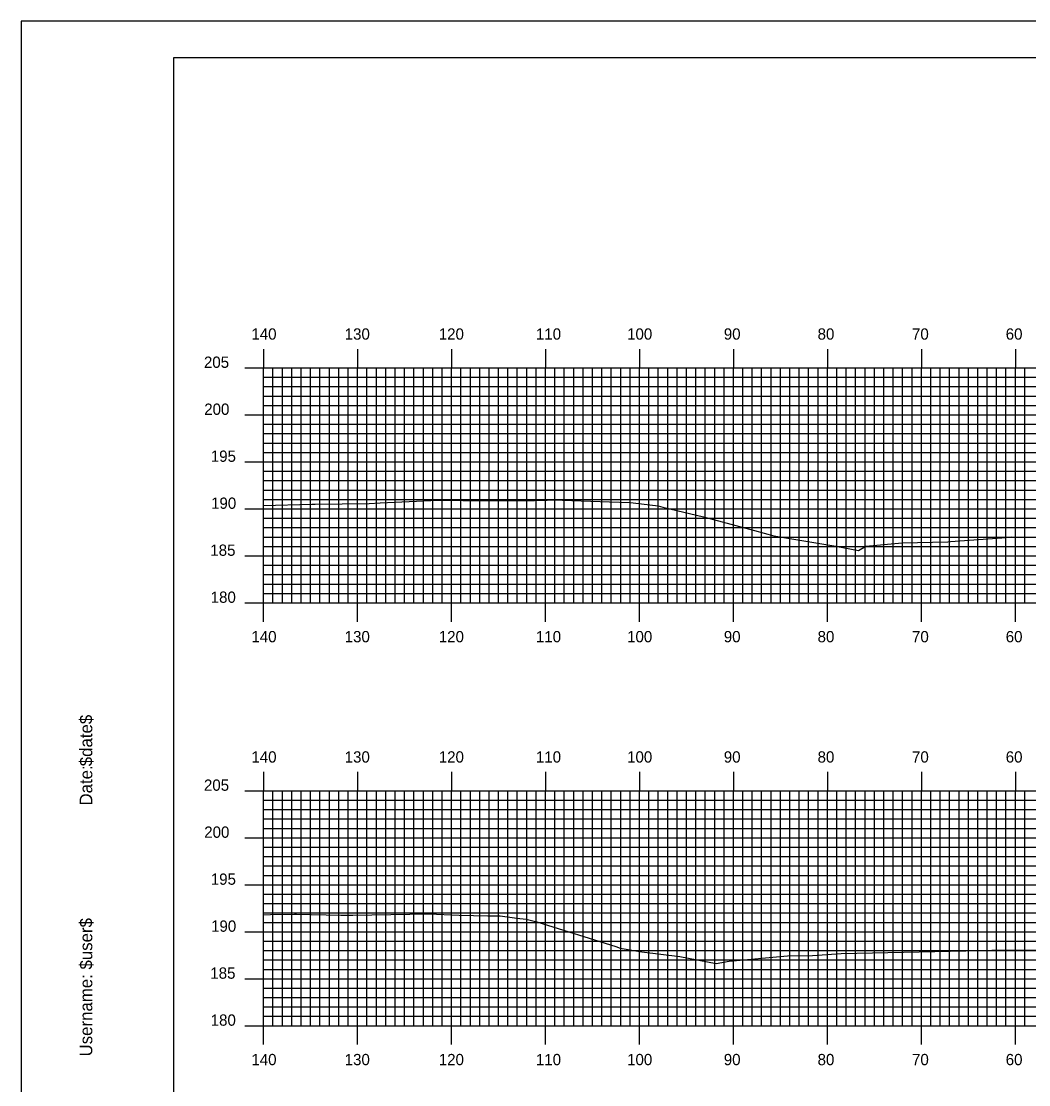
# Model space of a CAD drawing. Extents: x 1822392 to 1822735, y 442591 to 442811.
# Drawn here: x 1822392 to 1822499.2, y 442697.4 to 442810.5 of the extents above; entities that cross this region are included whole.
import ezdxf

# ---------------------------------------------------------------- set-up
doc = ezdxf.new("R2010")
doc.units = 0
for name, color, linetype in [('BORDER', 7, 'Continuous'), ('H_V ANNOTATION', 7, 'Continuous'), ('MAJOR', 7, 'Continuous'), ('MINOR', 7, 'Continuous'), ('PLOT BOUNDARY', 7, 'Continuous'), ('S_Roadway_Centerline', 7, 'Continuous')]:
    doc.layers.add(name, color=color, linetype=linetype)

msp = doc.modelspace()

# ---------------------------------------------------------------- linework, layer by layer
at = {"layer": 'BORDER'}
msp.add_lwpolyline([(1822408.17, 442596.67), (1822728.17, 442596.67), (1822728.17, 442806.67), (1822408.17, 442806.67)], close=True, dxfattribs=at)
at = {"layer": 'MAJOR'}
for p, q in [((1822417.77, 442775.67), (1822417.77, 442773.67)), ((1822427.77, 442775.67), (1822427.77, 442773.67)), ((1822437.77, 442775.67), (1822437.77, 442773.67)), ((1822447.77, 442775.67), (1822447.77, 442773.67)), ((1822457.77, 442775.67), (1822457.77, 442773.67)), ((1822467.77, 442775.67), (1822467.77, 442773.67)), ((1822477.77, 442775.67), (1822477.77, 442773.67)), ((1822487.77, 442775.67), (1822487.77, 442773.67)), ((1822497.77, 442775.67), (1822497.77, 442773.67)), ((1822415.77, 442773.67), (1822417.77, 442773.67)), ((1822417.77, 442773.67), (1822697.77, 442773.67)), ((1822417.77, 442748.67), (1822417.77, 442773.67)), ((1822417.77, 442748.67), (1822417.77, 442773.67)), ((1822417.77, 442773.67), (1822697.77, 442773.67)), ((1822427.77, 442748.67), (1822427.77, 442773.67)), ((1822437.77, 442748.67), (1822437.77, 442773.67)), ((1822447.77, 442748.67), (1822447.77, 442773.67)), ((1822457.77, 442748.67), (1822457.77, 442773.67)), ((1822467.77, 442748.67), (1822467.77, 442773.67)), ((1822477.77, 442748.67), (1822477.77, 442773.67)), ((1822487.77, 442748.67), (1822487.77, 442773.67)), ((1822497.77, 442748.67), (1822497.77, 442773.67)), ((1822415.77, 442768.67), (1822417.77, 442768.67)), ((1822417.77, 442768.67), (1822697.77, 442768.67)), ((1822415.77, 442763.67), (1822417.77, 442763.67)), ((1822417.77, 442763.67), (1822697.77, 442763.67)), ((1822415.77, 442758.67), (1822417.77, 442758.67)), ((1822417.77, 442758.67), (1822697.77, 442758.67)), ((1822415.77, 442753.67), (1822417.77, 442753.67)), ((1822417.77, 442753.67), (1822697.77, 442753.67)), ((1822415.77, 442748.67), (1822417.77, 442748.67)), ((1822417.77, 442748.67), (1822697.77, 442748.67)), ((1822417.77, 442748.67), (1822697.77, 442748.67)), ((1822417.77, 442746.66), (1822417.77, 442748.67)), ((1822427.77, 442746.66), (1822427.77, 442748.67)), ((1822437.77, 442746.66), (1822437.77, 442748.67)), ((1822447.77, 442746.66), (1822447.77, 442748.67)), ((1822457.77, 442746.66), (1822457.77, 442748.67)), ((1822467.77, 442746.66), (1822467.77, 442748.67)), ((1822477.77, 442746.66), (1822477.77, 442748.67)), ((1822487.77, 442746.66), (1822487.77, 442748.67)), ((1822497.77, 442746.66), (1822497.77, 442748.67)), ((1822417.77, 442730.67), (1822417.77, 442728.67)), ((1822427.77, 442730.67), (1822427.77, 442728.67)), ((1822437.77, 442730.67), (1822437.77, 442728.67)), ((1822447.77, 442730.67), (1822447.77, 442728.67)), ((1822457.77, 442730.67), (1822457.77, 442728.67)), ((1822467.77, 442730.67), (1822467.77, 442728.67)), ((1822477.77, 442730.67), (1822477.77, 442728.67)), ((1822487.77, 442730.67), (1822487.77, 442728.67)), ((1822497.77, 442730.67), (1822497.77, 442728.67)), ((1822415.77, 442728.67), (1822417.77, 442728.67)), ((1822417.77, 442728.67), (1822697.77, 442728.67)), ((1822417.77, 442703.67), (1822417.77, 442728.67)), ((1822417.77, 442703.67), (1822417.77, 442728.67)), ((1822417.77, 442728.67), (1822697.77, 442728.67)), ((1822427.77, 442703.67), (1822427.77, 442728.67)), ((1822437.77, 442703.67), (1822437.77, 442728.67)), ((1822447.77, 442703.67), (1822447.77, 442728.67)), ((1822457.77, 442703.67), (1822457.77, 442728.67)), ((1822467.77, 442703.67), (1822467.77, 442728.67)), ((1822477.77, 442703.67), (1822477.77, 442728.67)), ((1822487.77, 442703.67), (1822487.77, 442728.67)), ((1822497.77, 442703.67), (1822497.77, 442728.67)), ((1822415.77, 442723.67), (1822417.77, 442723.67)), ((1822417.77, 442723.67), (1822697.77, 442723.67)), ((1822415.77, 442718.67), (1822417.77, 442718.67)), ((1822417.77, 442718.67), (1822697.77, 442718.67)), ((1822415.77, 442713.67), (1822417.77, 442713.67)), ((1822417.77, 442713.67), (1822697.77, 442713.67)), ((1822415.77, 442708.67), (1822417.77, 442708.67)), ((1822417.77, 442708.67), (1822697.77, 442708.67)), ((1822415.77, 442703.67), (1822417.77, 442703.67)), ((1822417.77, 442703.67), (1822697.77, 442703.67)), ((1822417.77, 442703.67), (1822697.77, 442703.67)), ((1822417.77, 442701.66), (1822417.77, 442703.67)), ((1822427.77, 442701.66), (1822427.77, 442703.67)), ((1822437.77, 442701.66), (1822437.77, 442703.67)), ((1822447.77, 442701.66), (1822447.77, 442703.67)), ((1822457.77, 442701.66), (1822457.77, 442703.67)), ((1822467.77, 442701.66), (1822467.77, 442703.67)), ((1822477.77, 442701.66), (1822477.77, 442703.67)), ((1822487.77, 442701.66), (1822487.77, 442703.67)), ((1822497.77, 442701.66), (1822497.77, 442703.67))]:
    msp.add_line(p, q, dxfattribs=at)
at = {"layer": 'MINOR'}
for p, q in [((1822417.77, 442772.67), (1822697.77, 442772.67)), ((1822417.77, 442772.67), (1822419.77, 442772.67)), ((1822418.77, 442748.67), (1822418.77, 442773.67)), ((1822419.77, 442748.67), (1822419.77, 442773.67)), ((1822420.77, 442748.67), (1822420.77, 442773.67)), ((1822421.77, 442748.67), (1822421.77, 442773.67)), ((1822422.77, 442748.67), (1822422.77, 442773.67)), ((1822423.77, 442748.67), (1822423.77, 442773.67)), ((1822424.77, 442748.67), (1822424.77, 442773.67)), ((1822425.77, 442748.67), (1822425.77, 442773.67)), ((1822426.77, 442748.67), (1822426.77, 442773.67)), ((1822428.77, 442748.67), (1822428.77, 442773.67)), ((1822429.77, 442748.67), (1822429.77, 442773.67)), ((1822430.77, 442748.67), (1822430.77, 442773.67)), ((1822431.77, 442748.67), (1822431.77, 442773.67)), ((1822432.77, 442748.67), (1822432.77, 442773.67)), ((1822433.77, 442748.67), (1822433.77, 442773.67)), ((1822434.77, 442748.67), (1822434.77, 442773.67)), ((1822435.77, 442748.67), (1822435.77, 442773.67)), ((1822436.77, 442748.67), (1822436.77, 442773.67)), ((1822438.77, 442748.67), (1822438.77, 442773.67)), ((1822439.77, 442748.67), (1822439.77, 442773.67)), ((1822440.77, 442748.67), (1822440.77, 442773.67)), ((1822441.77, 442748.67), (1822441.77, 442773.67)), ((1822442.77, 442748.67), (1822442.77, 442773.67)), ((1822443.77, 442748.67), (1822443.77, 442773.67)), ((1822444.77, 442748.67), (1822444.77, 442773.67)), ((1822445.77, 442748.67), (1822445.77, 442773.67)), ((1822446.77, 442748.67), (1822446.77, 442773.67)), ((1822448.77, 442748.67), (1822448.77, 442773.67)), ((1822449.77, 442748.67), (1822449.77, 442773.67)), ((1822450.77, 442748.67), (1822450.77, 442773.67)), ((1822451.77, 442748.67), (1822451.77, 442773.67)), ((1822452.77, 442748.67), (1822452.77, 442773.67)), ((1822453.77, 442748.67), (1822453.77, 442773.67)), ((1822454.77, 442748.67), (1822454.77, 442773.67)), ((1822455.77, 442748.67), (1822455.77, 442773.67)), ((1822456.77, 442748.67), (1822456.77, 442773.67)), ((1822458.77, 442748.67), (1822458.77, 442773.67)), ((1822459.77, 442748.67), (1822459.77, 442773.67)), ((1822460.77, 442748.67), (1822460.77, 442773.67)), ((1822461.77, 442748.67), (1822461.77, 442773.67)), ((1822462.77, 442748.67), (1822462.77, 442773.67)), ((1822463.77, 442748.67), (1822463.77, 442773.67)), ((1822464.77, 442748.67), (1822464.77, 442773.67)), ((1822465.77, 442748.67), (1822465.77, 442773.67)), ((1822466.77, 442748.67), (1822466.77, 442773.67)), ((1822468.77, 442748.67), (1822468.77, 442773.67)), ((1822469.77, 442748.67), (1822469.77, 442773.67)), ((1822470.77, 442748.67), (1822470.77, 442773.67)), ((1822471.77, 442748.67), (1822471.77, 442773.67)), ((1822472.77, 442748.67), (1822472.77, 442773.67)), ((1822473.77, 442748.67), (1822473.77, 442773.67)), ((1822474.77, 442748.67), (1822474.77, 442773.67)), ((1822475.77, 442748.67), (1822475.77, 442773.67)), ((1822476.77, 442748.67), (1822476.77, 442773.67)), ((1822478.77, 442748.67), (1822478.77, 442773.67)), ((1822479.77, 442748.67), (1822479.77, 442773.67)), ((1822480.77, 442748.67), (1822480.77, 442773.67)), ((1822481.77, 442748.67), (1822481.77, 442773.67)), ((1822482.77, 442748.67), (1822482.77, 442773.67)), ((1822483.77, 442748.67), (1822483.77, 442773.67)), ((1822484.77, 442748.67), (1822484.77, 442773.67)), ((1822485.77, 442748.67), (1822485.77, 442773.67)), ((1822486.77, 442748.67), (1822486.77, 442773.67)), ((1822488.77, 442748.67), (1822488.77, 442773.67)), ((1822489.77, 442748.67), (1822489.77, 442773.67)), ((1822490.77, 442748.67), (1822490.77, 442773.67)), ((1822491.77, 442748.67), (1822491.77, 442773.67)), ((1822492.77, 442748.67), (1822492.77, 442773.67)), ((1822493.77, 442748.67), (1822493.77, 442773.67)), ((1822494.77, 442748.67), (1822494.77, 442773.67)), ((1822495.77, 442748.67), (1822495.77, 442773.67)), ((1822496.77, 442748.67), (1822496.77, 442773.67)), ((1822498.77, 442748.67), (1822498.77, 442773.67)), ((1822417.77, 442771.67), (1822697.77, 442771.67)), ((1822417.77, 442771.67), (1822419.77, 442771.67)), ((1822417.77, 442770.67), (1822697.77, 442770.67)), ((1822417.77, 442770.67), (1822419.77, 442770.67)), ((1822417.77, 442769.67), (1822697.77, 442769.67)), ((1822417.77, 442769.67), (1822419.77, 442769.67)), ((1822417.77, 442767.67), (1822697.77, 442767.67)), ((1822417.77, 442767.67), (1822419.77, 442767.67)), ((1822417.77, 442766.67), (1822697.77, 442766.67)), ((1822417.77, 442766.67), (1822419.77, 442766.67)), ((1822417.77, 442765.67), (1822697.77, 442765.67)), ((1822417.77, 442765.67), (1822419.77, 442765.67)), ((1822417.77, 442764.67), (1822697.77, 442764.67)), ((1822417.77, 442764.67), (1822419.77, 442764.67)), ((1822417.77, 442762.67), (1822697.77, 442762.67)), ((1822417.77, 442762.67), (1822419.77, 442762.67)), ((1822417.77, 442761.67), (1822697.77, 442761.67)), ((1822417.77, 442761.67), (1822419.77, 442761.67)), ((1822417.77, 442760.67), (1822697.77, 442760.67)), ((1822417.77, 442760.67), (1822419.77, 442760.67)), ((1822417.77, 442759.67), (1822697.77, 442759.67)), ((1822417.77, 442759.67), (1822419.77, 442759.67)), ((1822417.77, 442757.67), (1822697.77, 442757.67)), ((1822417.77, 442757.67), (1822419.77, 442757.67)), ((1822417.77, 442756.67), (1822697.77, 442756.67)), ((1822417.77, 442756.67), (1822419.77, 442756.67)), ((1822417.77, 442755.67), (1822697.77, 442755.67)), ((1822417.77, 442755.67), (1822419.77, 442755.67)), ((1822417.77, 442754.67), (1822697.77, 442754.67)), ((1822417.77, 442754.67), (1822419.77, 442754.67)), ((1822417.77, 442752.67), (1822697.77, 442752.67)), ((1822417.77, 442752.67), (1822419.77, 442752.67)), ((1822417.77, 442751.67), (1822697.77, 442751.67)), ((1822417.77, 442751.67), (1822419.77, 442751.67)), ((1822417.77, 442750.67), (1822697.77, 442750.67)), ((1822417.77, 442750.67), (1822419.77, 442750.67)), ((1822417.77, 442749.67), (1822697.77, 442749.67)), ((1822417.77, 442749.67), (1822419.77, 442749.67)), ((1822418.77, 442703.67), (1822418.77, 442728.67)), ((1822419.77, 442703.67), (1822419.77, 442728.67)), ((1822420.77, 442703.67), (1822420.77, 442728.67)), ((1822421.77, 442703.67), (1822421.77, 442728.67)), ((1822422.77, 442703.67), (1822422.77, 442728.67)), ((1822423.77, 442703.67), (1822423.77, 442728.67)), ((1822424.77, 442703.67), (1822424.77, 442728.67)), ((1822425.77, 442703.67), (1822425.77, 442728.67)), ((1822426.77, 442703.67), (1822426.77, 442728.67)), ((1822428.77, 442703.67), (1822428.77, 442728.67)), ((1822429.77, 442703.67), (1822429.77, 442728.67)), ((1822430.77, 442703.67), (1822430.77, 442728.67)), ((1822431.77, 442703.67), (1822431.77, 442728.67)), ((1822432.77, 442703.67), (1822432.77, 442728.67)), ((1822433.77, 442703.67), (1822433.77, 442728.67)), ((1822434.77, 442703.67), (1822434.77, 442728.67)), ((1822435.77, 442703.67), (1822435.77, 442728.67)), ((1822436.77, 442703.67), (1822436.77, 442728.67)), ((1822438.77, 442703.67), (1822438.77, 442728.67)), ((1822439.77, 442703.67), (1822439.77, 442728.67)), ((1822440.77, 442703.67), (1822440.77, 442728.67)), ((1822441.77, 442703.67), (1822441.77, 442728.67)), ((1822442.77, 442703.67), (1822442.77, 442728.67)), ((1822443.77, 442703.67), (1822443.77, 442728.67)), ((1822444.77, 442703.67), (1822444.77, 442728.67)), ((1822445.77, 442703.67), (1822445.77, 442728.67)), ((1822446.77, 442703.67), (1822446.77, 442728.67)), ((1822448.77, 442703.67), (1822448.77, 442728.67)), ((1822449.77, 442703.67), (1822449.77, 442728.67)), ((1822450.77, 442703.67), (1822450.77, 442728.67)), ((1822451.77, 442703.67), (1822451.77, 442728.67)), ((1822452.77, 442703.67), (1822452.77, 442728.67)), ((1822453.77, 442703.67), (1822453.77, 442728.67)), ((1822454.77, 442703.67), (1822454.77, 442728.67)), ((1822455.77, 442703.67), (1822455.77, 442728.67)), ((1822456.77, 442703.67), (1822456.77, 442728.67)), ((1822458.77, 442703.67), (1822458.77, 442728.67)), ((1822459.77, 442703.67), (1822459.77, 442728.67)), ((1822460.77, 442703.67), (1822460.77, 442728.67)), ((1822461.77, 442703.67), (1822461.77, 442728.67)), ((1822462.77, 442703.67), (1822462.77, 442728.67)), ((1822463.77, 442703.67), (1822463.77, 442728.67)), ((1822464.77, 442703.67), (1822464.77, 442728.67)), ((1822465.77, 442703.67), (1822465.77, 442728.67)), ((1822466.77, 442703.67), (1822466.77, 442728.67)), ((1822468.77, 442703.67), (1822468.77, 442728.67)), ((1822469.77, 442703.67), (1822469.77, 442728.67)), ((1822470.77, 442703.67), (1822470.77, 442728.67)), ((1822471.77, 442703.67), (1822471.77, 442728.67)), ((1822472.77, 442703.67), (1822472.77, 442728.67)), ((1822473.77, 442703.67), (1822473.77, 442728.67)), ((1822474.77, 442703.67), (1822474.77, 442728.67)), ((1822475.77, 442703.67), (1822475.77, 442728.67)), ((1822476.77, 442703.67), (1822476.77, 442728.67)), ((1822478.77, 442703.67), (1822478.77, 442728.67)), ((1822479.77, 442703.67), (1822479.77, 442728.67)), ((1822480.77, 442703.67), (1822480.77, 442728.67)), ((1822481.77, 442703.67), (1822481.77, 442728.67)), ((1822482.77, 442703.67), (1822482.77, 442728.67)), ((1822483.77, 442703.67), (1822483.77, 442728.67)), ((1822484.77, 442703.67), (1822484.77, 442728.67)), ((1822485.77, 442703.67), (1822485.77, 442728.67)), ((1822486.77, 442703.67), (1822486.77, 442728.67)), ((1822488.77, 442703.67), (1822488.77, 442728.67)), ((1822489.77, 442703.67), (1822489.77, 442728.67)), ((1822490.77, 442703.67), (1822490.77, 442728.67)), ((1822491.77, 442703.67), (1822491.77, 442728.67)), ((1822492.77, 442703.67), (1822492.77, 442728.67)), ((1822493.77, 442703.67), (1822493.77, 442728.67)), ((1822494.77, 442703.67), (1822494.77, 442728.67)), ((1822495.77, 442703.67), (1822495.77, 442728.67)), ((1822496.77, 442703.67), (1822496.77, 442728.67)), ((1822498.77, 442703.67), (1822498.77, 442728.67)), ((1822417.77, 442727.67), (1822697.77, 442727.67)), ((1822417.77, 442727.67), (1822419.77, 442727.67)), ((1822417.77, 442726.67), (1822697.77, 442726.67)), ((1822417.77, 442726.67), (1822419.77, 442726.67)), ((1822417.77, 442725.67), (1822697.77, 442725.67)), ((1822417.77, 442725.67), (1822419.77, 442725.67)), ((1822417.77, 442724.67), (1822697.77, 442724.67)), ((1822417.77, 442724.67), (1822419.77, 442724.67)), ((1822417.77, 442722.67), (1822697.77, 442722.67)), ((1822417.77, 442722.67), (1822419.77, 442722.67)), ((1822417.77, 442721.67), (1822697.77, 442721.67)), ((1822417.77, 442721.67), (1822419.77, 442721.67)), ((1822417.77, 442720.67), (1822697.77, 442720.67)), ((1822417.77, 442720.67), (1822419.77, 442720.67)), ((1822417.77, 442719.67), (1822697.77, 442719.67)), ((1822417.77, 442719.67), (1822419.77, 442719.67)), ((1822417.77, 442717.67), (1822697.77, 442717.67)), ((1822417.77, 442717.67), (1822419.77, 442717.67)), ((1822417.77, 442716.67), (1822697.77, 442716.67)), ((1822417.77, 442716.67), (1822419.77, 442716.67)), ((1822417.77, 442715.67), (1822697.77, 442715.67)), ((1822417.77, 442715.67), (1822419.77, 442715.67)), ((1822417.77, 442714.67), (1822697.77, 442714.67)), ((1822417.77, 442714.67), (1822419.77, 442714.67)), ((1822417.77, 442712.67), (1822697.77, 442712.67)), ((1822417.77, 442712.67), (1822419.77, 442712.67)), ((1822417.77, 442711.67), (1822697.77, 442711.67)), ((1822417.77, 442711.67), (1822419.77, 442711.67)), ((1822417.77, 442710.67), (1822697.77, 442710.67)), ((1822417.77, 442710.67), (1822419.77, 442710.67)), ((1822417.77, 442709.67), (1822697.77, 442709.67)), ((1822417.77, 442709.67), (1822419.77, 442709.67)), ((1822417.77, 442707.67), (1822697.77, 442707.67)), ((1822417.77, 442707.67), (1822419.77, 442707.67)), ((1822417.77, 442706.67), (1822697.77, 442706.67)), ((1822417.77, 442706.67), (1822419.77, 442706.67)), ((1822417.77, 442705.67), (1822697.77, 442705.67)), ((1822417.77, 442705.67), (1822419.77, 442705.67)), ((1822417.77, 442704.67), (1822697.77, 442704.67)), ((1822417.77, 442704.67), (1822419.77, 442704.67))]:
    msp.add_line(p, q, dxfattribs=at)
at = {"layer": 'PLOT BOUNDARY'}
msp.add_lwpolyline([(1822391.98, 442590.55), (1822731.98, 442590.55), (1822731.98, 442810.55), (1822391.98, 442810.55)], close=True, dxfattribs=at)
at = {"layer": 'S_Roadway_Centerline'}
for points in [[(1822417.77, 442759.04), (1822422.9, 442759.17), (1822423.24, 442759.18), (1822429, 442759.24), (1822430.19, 442759.29), (1822435.58, 442759.57), (1822435.69, 442759.6), (1822438.96, 442759.56), (1822446.59, 442759.55), (1822449.29, 442759.62), (1822449.57, 442759.59), (1822454.58, 442759.41), (1822456.75, 442759.33), (1822457.11, 442759.29), (1822459.76, 442758.98), (1822460.25, 442758.83), (1822464.59, 442757.81), (1822470, 442756.36), (1822472.07, 442755.8), (1822478.66, 442754.68), (1822481.07, 442754.23), (1822481.85, 442754.71), (1822485.73, 442755.04), (1822490.59, 442755.16), (1822490.88, 442755.19), (1822496.33, 442755.6), (1822497.4, 442755.69), (1822499.43, 442755.66)], [(1822417.77, 442715.48), (1822418.5, 442715.5), (1822421.07, 442715.54), (1822421.26, 442715.55), (1822425.98, 442715.43), (1822427.28, 442715.43), (1822435.37, 442715.57), (1822438.59, 442715.44), (1822441.63, 442715.35), (1822442.94, 442715.36), (1822444.71, 442715.13), (1822445.7, 442715), (1822446.86, 442714.74), (1822455.25, 442712.11), (1822455.7, 442711.94), (1822458.02, 442711.54), (1822462.07, 442711.03), (1822465.94, 442710.29), (1822467.31, 442710.55), (1822473.51, 442711.12), (1822476.17, 442711.14), (1822479.24, 442711.35), (1822494.15, 442711.67), (1822495.25, 442711.71), (1822498.65, 442711.71), (1822510.54, 442711.77)]]:
    msp.add_lwpolyline(points, dxfattribs=at)

# ---------------------------------------------------------------- texts
at = {"layer": 'BORDER'}
for s, p in [('$date$', (1822399.54, 442731.28)), ('Date:', (1822399.54, 442727.1)), ('$user$', (1822399.54, 442709.65)), ('Username:', (1822399.54, 442700.4))]:
    msp.add_text(s, height=1.339, rotation=90, dxfattribs=at).set_placement(p)
at = {"layer": 'H_V ANNOTATION'}
for s, p in [('140', (1822416.47, 442776.67)), ('130', (1822426.4, 442776.67)), ('120', (1822436.41, 442776.67)), ('110', (1822446.75, 442776.67)), ('100', (1822456.45, 442776.67)), ('90', (1822466.74, 442776.67)), ('80', (1822476.72, 442776.67)), ('70', (1822486.77, 442776.67)), ('60', (1822496.74, 442776.67)), ('205', (1822411.42, 442773.67)), ('200', (1822411.45, 442768.67)), ('195', (1822412.15, 442763.67)), ('190', (1822412.18, 442758.67)), ('185', (1822412.1, 442753.67)), ('180', (1822412.14, 442748.67)), ('140', (1822416.47, 442744.47)), ('130', (1822426.4, 442744.47)), ('120', (1822436.41, 442744.47)), ('110', (1822446.75, 442744.47)), ('100', (1822456.45, 442744.47)), ('90', (1822466.74, 442744.47)), ('80', (1822476.72, 442744.47)), ('70', (1822486.77, 442744.47)), ('60', (1822496.74, 442744.47)), ('140', (1822416.47, 442731.67)), ('130', (1822426.4, 442731.67)), ('120', (1822436.41, 442731.67)), ('110', (1822446.75, 442731.67)), ('100', (1822456.45, 442731.67)), ('90', (1822466.74, 442731.67)), ('80', (1822476.72, 442731.67)), ('70', (1822486.77, 442731.67)), ('60', (1822496.74, 442731.67)), ('205', (1822411.42, 442728.67)), ('200', (1822411.45, 442723.67)), ('195', (1822412.15, 442718.67)), ('190', (1822412.18, 442713.67)), ('185', (1822412.1, 442708.67)), ('180', (1822412.14, 442703.67)), ('140', (1822416.47, 442699.47)), ('130', (1822426.4, 442699.47)), ('120', (1822436.41, 442699.47)), ('110', (1822446.75, 442699.47)), ('100', (1822456.45, 442699.47)), ('90', (1822466.74, 442699.47)), ('80', (1822476.72, 442699.47)), ('70', (1822486.77, 442699.47)), ('60', (1822496.74, 442699.47))]:
    msp.add_text(s, height=1.2, dxfattribs=at).set_placement(p)
at = {"layer": 'MAJOR'}
for p in [(1822417.76, 442748.67), (1822417.76, 442703.67)]:
    msp.add_text('-', height=0.012, dxfattribs=at).set_placement(p)
at = {"layer": 'S_Roadway_Centerline'}
for s, p in [('C', (1822435.68, 442759.6)), ('L', (1822435.68, 442759.59)), ('C', (1822421.25, 442715.55)), ('L', (1822421.25, 442715.54))]:
    msp.add_text(s, height=0.0146, dxfattribs=at).set_placement(p)

doc.saveas('drawing.dxf')
